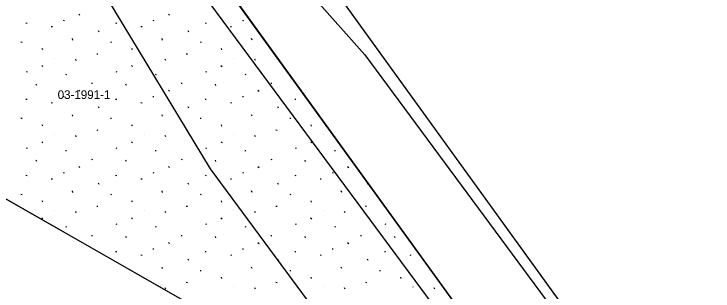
# Model space of a CAD drawing. Extents: x 413946 to 415528, y 4453939 to 4454944.
# Drawn here: x 414117.8 to 414198.6, y 4454721 to 4454753 of the extents above; entities that cross this region are included whole.
import ezdxf

# ---------------------------------------------------------------- set-up
doc = ezdxf.new("R2010")
doc.units = 0
for name, color, linetype in [('0_KADASTRO', 7, 'Continuous'), ('HAT_ENERJI_NAKIL_HAT', 7, 'Continuous'), ('KST_ENERJI_NAKIL_HAT', 7, 'Continuous'), ('Level 28', 7, 'Continuous'), ('Level 41', 7, 'Continuous'), ('Level 54', 7, 'Continuous')]:
    doc.layers.add(name, color=color, linetype=linetype)

msp = doc.modelspace()

# ---------------------------------------------------------------- linework, layer by layer
at = {"layer": '0_KADASTRO'}
for points in [[(414096.99, 4454835.77), (414098.7, 4454839.14), (414238.98, 4454892.53), (414254.93, 4454896.1), (414267.24, 4454897.45), (414291.64, 4454897.36), (414301.38, 4454895.97), (414237.57, 4454666.8), (414236.56, 4454663.13), (414213.19, 4454675.19), (414204.39, 4454687.27), (414188.47, 4454709.34), (414167.47, 4454738.38)], [(414085.37, 4454749.55), (414107.18, 4454790.27), (414110.22, 4454795.94), (414114.42, 4454794.63), (414180.37, 4454703.49), (414185.88, 4454695.87), (414185.72, 4454695.34), (414184.91, 4454692.77), (414168.2, 4454702.3), (414160.59, 4454706.64)]]:
    msp.add_lwpolyline(points, close=True, dxfattribs=at)
at = {"layer": 'HAT_ENERJI_NAKIL_HAT'}
msp.add_lwpolyline([(414658.516, 4453939.478), (414647.224, 4454070.234), (413999.883, 4454943.957)], dxfattribs=at)
at = {"layer": 'KST_ENERJI_NAKIL_HAT'}
for p, q in [((414107.065, 4454805.782), (414158.371, 4454748.301)), ((414140.517, 4454735.108), (414100.636, 4454801.021)), ((414158.371, 4454748.301), (414184.473, 4454712.979)), ((414230.556, 4454613.267), (414140.517, 4454735.108))]:
    msp.add_line(p, q, dxfattribs=at)
at = {"layer": 'Level 28'}
for p, q in [((414167.47, 4454738.38), (414096.99, 4454835.77)), ((414114.42, 4454794.63), (414185.88, 4454695.87)), ((414184.91, 4454692.77), (414085.37, 4454749.55)), ((414188.47, 4454709.34), (414167.47, 4454738.38))]:
    msp.add_line(p, q, dxfattribs=at)
at = {"layer": 'Level 41'}
for p, q in [((414125.262, 4454752.989), (414125.389, 4454752.889)), ((414125.262, 4454752.989), (414125.389, 4454752.889)), ((414135.63, 4454752.989), (414135.757, 4454752.889)), ((414135.63, 4454752.989), (414135.757, 4454752.889)), ((414119.162, 4454751.979), (414119.288, 4454751.956)), ((414119.162, 4454751.979), (414119.288, 4454751.956)), ((414122.091, 4454751.569), (414122.217, 4454751.545)), ((414122.091, 4454751.569), (414122.217, 4454751.545)), ((414123.467, 4454752.283), (414123.593, 4454752.26)), ((414123.467, 4454752.283), (414123.593, 4454752.26)), ((414129.53, 4454751.979), (414129.656, 4454751.956)), ((414129.53, 4454751.979), (414129.656, 4454751.956)), ((414132.459, 4454751.569), (414132.585, 4454751.545)), ((414132.459, 4454751.569), (414132.585, 4454751.545)), ((414133.835, 4454752.283), (414133.961, 4454752.26)), ((414133.835, 4454752.283), (414133.961, 4454752.26)), ((414139.898, 4454751.979), (414140.024, 4454751.956)), ((414139.898, 4454751.979), (414140.024, 4454751.956)), ((414142.827, 4454751.569), (414142.953, 4454751.545)), ((414142.827, 4454751.569), (414142.953, 4454751.545)), ((414144.203, 4454752.283), (414144.329, 4454752.26)), ((414144.203, 4454752.283), (414144.329, 4454752.26)), ((414127.627, 4454750.91), (414127.561, 4454751.072)), ((414127.627, 4454750.91), (414127.561, 4454751.072)), ((414137.995, 4454750.91), (414137.929, 4454751.072)), ((414137.995, 4454750.91), (414137.929, 4454751.072)), ((414124.596, 4454749.995), (414124.531, 4454750.159)), ((414124.596, 4454749.995), (414124.531, 4454750.159)), ((414134.964, 4454749.995), (414134.899, 4454750.159)), ((414134.964, 4454749.995), (414134.899, 4454750.159)), ((414145.332, 4454749.995), (414145.267, 4454750.159)), ((414145.332, 4454749.995), (414145.267, 4454750.159)), ((414118.578, 4454749.775), (414118.704, 4454749.751)), ((414118.578, 4454749.775), (414118.704, 4454749.751)), ((414128.946, 4454749.775), (414129.072, 4454749.751)), ((414128.946, 4454749.775), (414129.072, 4454749.751)), ((414139.314, 4454749.775), (414139.44, 4454749.751)), ((414139.314, 4454749.775), (414139.44, 4454749.751)), ((414121.1, 4454748.846), (414121.036, 4454749.007)), ((414121.1, 4454748.846), (414121.036, 4454749.007)), ((414127.342, 4454748.407), (414127.468, 4454748.383)), ((414127.342, 4454748.407), (414127.468, 4454748.383)), ((414131.468, 4454748.846), (414131.404, 4454749.007)), ((414131.468, 4454748.846), (414131.404, 4454749.007)), ((414137.71, 4454748.407), (414137.836, 4454748.383)), ((414137.71, 4454748.407), (414137.836, 4454748.383)), ((414141.836, 4454748.846), (414141.772, 4454749.007)), ((414141.836, 4454748.846), (414141.772, 4454749.007)), ((414122.458, 4454747.882), (414122.466, 4454747.881)), ((414122.458, 4454747.882), (414122.466, 4454747.881)), ((414124.977, 4454747.613), (414124.912, 4454747.775)), ((414124.977, 4454747.613), (414124.912, 4454747.775)), ((414132.826, 4454747.882), (414132.834, 4454747.881)), ((414132.826, 4454747.882), (414132.834, 4454747.881)), ((414135.345, 4454747.613), (414135.28, 4454747.775)), ((414135.345, 4454747.613), (414135.28, 4454747.775)), ((414143.194, 4454747.882), (414143.202, 4454747.881)), ((414143.194, 4454747.882), (414143.202, 4454747.881)), ((414145.713, 4454747.613), (414145.648, 4454747.775)), ((414145.713, 4454747.613), (414145.648, 4454747.775)), ((414120.983, 4454747.044), (414121.11, 4454746.945)), ((414120.983, 4454747.044), (414121.11, 4454746.945)), ((414131.351, 4454747.044), (414131.478, 4454746.945)), ((414131.351, 4454747.044), (414131.478, 4454746.945)), ((414141.719, 4454747.044), (414141.846, 4454746.945)), ((414141.719, 4454747.044), (414141.846, 4454746.945)), ((414119.189, 4454746.339), (414119.315, 4454746.314)), ((414119.189, 4454746.339), (414119.315, 4454746.314)), ((414123.737, 4454746.045), (414123.863, 4454746.021)), ((414123.737, 4454746.045), (414123.863, 4454746.021)), ((414129.557, 4454746.339), (414129.683, 4454746.314)), ((414129.557, 4454746.339), (414129.683, 4454746.314)), ((414134.105, 4454746.045), (414134.231, 4454746.021)), ((414134.105, 4454746.045), (414134.231, 4454746.021)), ((414139.925, 4454746.339), (414140.051, 4454746.314)), ((414139.925, 4454746.339), (414140.051, 4454746.314)), ((414144.473, 4454746.045), (414144.599, 4454746.021)), ((414144.473, 4454746.045), (414144.599, 4454746.021)), ((414126.737, 4454745.021), (414126.862, 4454744.996)), ((414126.737, 4454745.021), (414126.862, 4454744.996)), ((414137.105, 4454745.021), (414137.23, 4454744.996)), ((414137.105, 4454745.021), (414137.23, 4454744.996)), ((414147.473, 4454745.021), (414147.598, 4454744.996)), ((414147.473, 4454745.021), (414147.598, 4454744.996)), ((414120.402, 4454744.741), (414120.337, 4454744.903)), ((414120.402, 4454744.741), (414120.337, 4454744.903)), ((414130.77, 4454744.741), (414130.705, 4454744.903)), ((414130.77, 4454744.741), (414130.705, 4454744.903)), ((414141.138, 4454744.741), (414141.073, 4454744.903)), ((414141.138, 4454744.741), (414141.073, 4454744.903)), ((414123.467, 4454743.477), (414123.593, 4454743.454)), ((414123.467, 4454743.477), (414123.593, 4454743.454)), ((414125.262, 4454744.183), (414125.389, 4454744.083)), ((414125.262, 4454744.183), (414125.389, 4454744.083)), ((414133.835, 4454743.477), (414133.961, 4454743.454)), ((414133.835, 4454743.477), (414133.961, 4454743.454)), ((414135.63, 4454744.183), (414135.757, 4454744.083)), ((414135.63, 4454744.183), (414135.757, 4454744.083)), ((414144.203, 4454743.477), (414144.329, 4454743.454)), ((414144.203, 4454743.477), (414144.329, 4454743.454)), ((414145.998, 4454744.183), (414146.125, 4454744.083)), ((414145.998, 4454744.183), (414146.125, 4454744.083)), ((414119.162, 4454743.173), (414119.288, 4454743.15)), ((414119.162, 4454743.173), (414119.288, 4454743.15)), ((414122.091, 4454742.763), (414122.217, 4454742.739)), ((414122.091, 4454742.763), (414122.217, 4454742.739)), ((414129.53, 4454743.173), (414129.656, 4454743.15)), ((414129.53, 4454743.173), (414129.656, 4454743.15)), ((414132.459, 4454742.763), (414132.585, 4454742.739)), ((414132.459, 4454742.763), (414132.585, 4454742.739)), ((414139.898, 4454743.173), (414140.024, 4454743.15)), ((414139.898, 4454743.173), (414140.024, 4454743.15)), ((414142.827, 4454742.763), (414142.953, 4454742.739)), ((414142.827, 4454742.763), (414142.953, 4454742.739)), ((414150.266, 4454743.173), (414150.392, 4454743.15)), ((414150.266, 4454743.173), (414150.392, 4454743.15)), ((414127.627, 4454742.104), (414127.561, 4454742.266)), ((414127.627, 4454742.104), (414127.561, 4454742.266)), ((414137.995, 4454742.104), (414137.929, 4454742.266)), ((414137.995, 4454742.104), (414137.929, 4454742.266)), ((414148.363, 4454742.104), (414148.297, 4454742.266)), ((414148.363, 4454742.104), (414148.297, 4454742.266)), ((414124.596, 4454741.189), (414124.531, 4454741.353)), ((414124.596, 4454741.189), (414124.531, 4454741.353)), ((414134.964, 4454741.189), (414134.899, 4454741.353)), ((414134.964, 4454741.189), (414134.899, 4454741.353)), ((414145.332, 4454741.189), (414145.267, 4454741.353)), ((414145.332, 4454741.189), (414145.267, 4454741.353)), ((414118.578, 4454740.969), (414118.704, 4454740.945)), ((414118.578, 4454740.969), (414118.704, 4454740.945)), ((414121.1, 4454740.04), (414121.036, 4454740.201)), ((414121.1, 4454740.04), (414121.036, 4454740.201)), ((414128.946, 4454740.969), (414129.072, 4454740.945)), ((414128.946, 4454740.969), (414129.072, 4454740.945)), ((414131.468, 4454740.04), (414131.404, 4454740.201)), ((414131.468, 4454740.04), (414131.404, 4454740.201)), ((414139.314, 4454740.969), (414139.44, 4454740.945)), ((414139.314, 4454740.969), (414139.44, 4454740.945)), ((414141.836, 4454740.04), (414141.772, 4454740.201)), ((414141.836, 4454740.04), (414141.772, 4454740.201)), ((414149.682, 4454740.969), (414149.808, 4454740.945)), ((414149.682, 4454740.969), (414149.808, 4454740.945)), ((414152.204, 4454740.04), (414152.14, 4454740.201)), ((414152.204, 4454740.04), (414152.14, 4454740.201)), ((414127.342, 4454739.601), (414127.468, 4454739.577)), ((414127.342, 4454739.601), (414127.468, 4454739.577)), ((414137.71, 4454739.601), (414137.836, 4454739.577)), ((414137.71, 4454739.601), (414137.836, 4454739.577)), ((414148.078, 4454739.601), (414148.204, 4454739.577)), ((414148.078, 4454739.601), (414148.204, 4454739.577)), ((414122.458, 4454739.076), (414122.466, 4454739.075)), ((414122.458, 4454739.076), (414122.466, 4454739.075)), ((414124.977, 4454738.807), (414124.912, 4454738.969)), ((414124.977, 4454738.807), (414124.912, 4454738.969)), ((414132.826, 4454739.076), (414132.834, 4454739.075)), ((414132.826, 4454739.076), (414132.834, 4454739.075)), ((414135.345, 4454738.807), (414135.28, 4454738.969)), ((414135.345, 4454738.807), (414135.28, 4454738.969)), ((414143.194, 4454739.076), (414143.202, 4454739.075)), ((414143.194, 4454739.076), (414143.202, 4454739.075)), ((414145.713, 4454738.807), (414145.648, 4454738.969)), ((414145.713, 4454738.807), (414145.648, 4454738.969)), ((414153.562, 4454739.076), (414153.57, 4454739.075)), ((414153.562, 4454739.076), (414153.57, 4454739.075)), ((414120.983, 4454738.238), (414121.11, 4454738.139)), ((414120.983, 4454738.238), (414121.11, 4454738.139)), ((414131.351, 4454738.238), (414131.478, 4454738.139)), ((414131.351, 4454738.238), (414131.478, 4454738.139)), ((414141.719, 4454738.238), (414141.846, 4454738.139)), ((414141.719, 4454738.238), (414141.846, 4454738.139)), ((414152.087, 4454738.238), (414152.214, 4454738.139)), ((414152.087, 4454738.238), (414152.214, 4454738.139)), ((414119.189, 4454737.533), (414119.315, 4454737.508)), ((414119.189, 4454737.533), (414119.315, 4454737.508)), ((414123.737, 4454737.239), (414123.863, 4454737.215)), ((414123.737, 4454737.239), (414123.863, 4454737.215)), ((414129.557, 4454737.533), (414129.683, 4454737.508)), ((414129.557, 4454737.533), (414129.683, 4454737.508)), ((414134.105, 4454737.239), (414134.231, 4454737.215)), ((414134.105, 4454737.239), (414134.231, 4454737.215)), ((414139.925, 4454737.533), (414140.051, 4454737.508)), ((414139.925, 4454737.533), (414140.051, 4454737.508)), ((414144.473, 4454737.239), (414144.599, 4454737.215)), ((414144.473, 4454737.239), (414144.599, 4454737.215)), ((414150.293, 4454737.533), (414150.419, 4454737.508)), ((414150.293, 4454737.533), (414150.419, 4454737.508)), ((414154.841, 4454737.239), (414154.967, 4454737.215)), ((414154.841, 4454737.239), (414154.967, 4454737.215)), ((414126.737, 4454736.215), (414126.862, 4454736.19)), ((414126.737, 4454736.215), (414126.862, 4454736.19)), ((414137.105, 4454736.215), (414137.23, 4454736.19)), ((414137.105, 4454736.215), (414137.23, 4454736.19)), ((414147.473, 4454736.215), (414147.598, 4454736.19)), ((414147.473, 4454736.215), (414147.598, 4454736.19)), ((414120.402, 4454735.935), (414120.337, 4454736.097)), ((414120.402, 4454735.935), (414120.337, 4454736.097)), ((414125.262, 4454735.377), (414125.389, 4454735.277)), ((414125.262, 4454735.377), (414125.389, 4454735.277)), ((414130.77, 4454735.935), (414130.705, 4454736.097)), ((414130.77, 4454735.935), (414130.705, 4454736.097)), ((414135.63, 4454735.377), (414135.757, 4454735.277)), ((414135.63, 4454735.377), (414135.757, 4454735.277)), ((414141.138, 4454735.935), (414141.073, 4454736.097)), ((414141.138, 4454735.935), (414141.073, 4454736.097)), ((414145.998, 4454735.377), (414146.125, 4454735.277)), ((414145.998, 4454735.377), (414146.125, 4454735.277)), ((414151.506, 4454735.935), (414151.441, 4454736.097)), ((414151.506, 4454735.935), (414151.441, 4454736.097)), ((414156.366, 4454735.377), (414156.493, 4454735.277)), ((414156.366, 4454735.377), (414156.493, 4454735.277)), ((414123.467, 4454734.671), (414123.593, 4454734.648)), ((414123.467, 4454734.671), (414123.593, 4454734.648)), ((414133.835, 4454734.671), (414133.961, 4454734.648)), ((414133.835, 4454734.671), (414133.961, 4454734.648)), ((414144.203, 4454734.671), (414144.329, 4454734.648)), ((414144.203, 4454734.671), (414144.329, 4454734.648)), ((414154.571, 4454734.671), (414154.697, 4454734.648)), ((414154.571, 4454734.671), (414154.697, 4454734.648)), ((414119.162, 4454734.367), (414119.288, 4454734.344)), ((414119.162, 4454734.367), (414119.288, 4454734.344)), ((414122.091, 4454733.957), (414122.217, 4454733.933)), ((414122.091, 4454733.957), (414122.217, 4454733.933)), ((414129.53, 4454734.367), (414129.656, 4454734.344)), ((414129.53, 4454734.367), (414129.656, 4454734.344)), ((414132.459, 4454733.957), (414132.585, 4454733.933)), ((414132.459, 4454733.957), (414132.585, 4454733.933)), ((414139.898, 4454734.367), (414140.024, 4454734.344)), ((414139.898, 4454734.367), (414140.024, 4454734.344)), ((414142.827, 4454733.957), (414142.953, 4454733.933)), ((414142.827, 4454733.957), (414142.953, 4454733.933)), ((414150.266, 4454734.367), (414150.392, 4454734.344)), ((414150.266, 4454734.367), (414150.392, 4454734.344)), ((414153.195, 4454733.957), (414153.321, 4454733.933)), ((414153.195, 4454733.957), (414153.321, 4454733.933)), ((414127.627, 4454733.298), (414127.561, 4454733.46)), ((414127.627, 4454733.298), (414127.561, 4454733.46)), ((414137.995, 4454733.298), (414137.929, 4454733.46)), ((414137.995, 4454733.298), (414137.929, 4454733.46)), ((414148.363, 4454733.298), (414148.297, 4454733.46)), ((414148.363, 4454733.298), (414148.297, 4454733.46)), ((414158.731, 4454733.298), (414158.665, 4454733.46)), ((414158.731, 4454733.298), (414158.665, 4454733.46)), ((414118.578, 4454732.163), (414118.704, 4454732.139)), ((414118.578, 4454732.163), (414118.704, 4454732.139)), ((414124.596, 4454732.383), (414124.531, 4454732.547)), ((414124.596, 4454732.383), (414124.531, 4454732.547)), ((414128.946, 4454732.163), (414129.072, 4454732.139)), ((414128.946, 4454732.163), (414129.072, 4454732.139)), ((414134.964, 4454732.383), (414134.899, 4454732.547)), ((414134.964, 4454732.383), (414134.899, 4454732.547)), ((414139.314, 4454732.163), (414139.44, 4454732.139)), ((414139.314, 4454732.163), (414139.44, 4454732.139)), ((414145.332, 4454732.383), (414145.267, 4454732.547)), ((414145.332, 4454732.383), (414145.267, 4454732.547)), ((414149.682, 4454732.163), (414149.808, 4454732.139)), ((414149.682, 4454732.163), (414149.808, 4454732.139)), ((414155.7, 4454732.383), (414155.635, 4454732.547)), ((414155.7, 4454732.383), (414155.635, 4454732.547)), ((414121.1, 4454731.234), (414121.036, 4454731.395)), ((414121.1, 4454731.234), (414121.036, 4454731.395)), ((414131.468, 4454731.234), (414131.404, 4454731.395)), ((414131.468, 4454731.234), (414131.404, 4454731.395)), ((414141.836, 4454731.234), (414141.772, 4454731.395)), ((414141.836, 4454731.234), (414141.772, 4454731.395)), ((414152.204, 4454731.234), (414152.14, 4454731.395)), ((414152.204, 4454731.234), (414152.14, 4454731.395)), ((414127.342, 4454730.795), (414127.468, 4454730.771)), ((414127.342, 4454730.795), (414127.468, 4454730.771)), ((414137.71, 4454730.795), (414137.836, 4454730.771)), ((414137.71, 4454730.795), (414137.836, 4454730.771)), ((414148.078, 4454730.795), (414148.204, 4454730.771)), ((414148.078, 4454730.795), (414148.204, 4454730.771)), ((414158.446, 4454730.795), (414158.572, 4454730.771)), ((414158.446, 4454730.795), (414158.572, 4454730.771)), ((414122.458, 4454730.27), (414122.466, 4454730.269)), ((414122.458, 4454730.27), (414122.466, 4454730.269)), ((414124.977, 4454730.001), (414124.912, 4454730.163)), ((414124.977, 4454730.001), (414124.912, 4454730.163)), ((414132.826, 4454730.27), (414132.834, 4454730.269)), ((414132.826, 4454730.27), (414132.834, 4454730.269)), ((414135.345, 4454730.001), (414135.28, 4454730.163)), ((414135.345, 4454730.001), (414135.28, 4454730.163)), ((414143.194, 4454730.27), (414143.202, 4454730.269)), ((414143.194, 4454730.27), (414143.202, 4454730.269)), ((414145.713, 4454730.001), (414145.648, 4454730.163)), ((414145.713, 4454730.001), (414145.648, 4454730.163)), ((414153.562, 4454730.27), (414153.57, 4454730.269)), ((414153.562, 4454730.27), (414153.57, 4454730.269)), ((414156.081, 4454730.001), (414156.016, 4454730.163)), ((414156.081, 4454730.001), (414156.016, 4454730.163)), ((414120.983, 4454729.432), (414121.11, 4454729.333)), ((414120.983, 4454729.432), (414121.11, 4454729.333)), ((414131.351, 4454729.432), (414131.478, 4454729.333)), ((414131.351, 4454729.432), (414131.478, 4454729.333)), ((414141.719, 4454729.432), (414141.846, 4454729.333)), ((414141.719, 4454729.432), (414141.846, 4454729.333)), ((414152.087, 4454729.432), (414152.214, 4454729.333)), ((414152.087, 4454729.432), (414152.214, 4454729.333)), ((414123.737, 4454728.433), (414123.863, 4454728.409)), ((414123.737, 4454728.433), (414123.863, 4454728.409)), ((414129.557, 4454728.727), (414129.683, 4454728.702)), ((414129.557, 4454728.727), (414129.683, 4454728.702)), ((414134.105, 4454728.433), (414134.231, 4454728.409)), ((414134.105, 4454728.433), (414134.231, 4454728.409)), ((414139.925, 4454728.727), (414140.051, 4454728.702)), ((414139.925, 4454728.727), (414140.051, 4454728.702)), ((414144.473, 4454728.433), (414144.599, 4454728.409)), ((414144.473, 4454728.433), (414144.599, 4454728.409)), ((414150.293, 4454728.727), (414150.419, 4454728.702)), ((414150.293, 4454728.727), (414150.419, 4454728.702)), ((414154.841, 4454728.433), (414154.967, 4454728.409)), ((414154.841, 4454728.433), (414154.967, 4454728.409)), ((414160.661, 4454728.727), (414160.787, 4454728.702)), ((414160.661, 4454728.727), (414160.787, 4454728.702)), ((414126.737, 4454727.409), (414126.862, 4454727.384)), ((414126.737, 4454727.409), (414126.862, 4454727.384)), ((414130.77, 4454727.129), (414130.705, 4454727.291)), ((414130.77, 4454727.129), (414130.705, 4454727.291)), ((414137.105, 4454727.409), (414137.23, 4454727.384)), ((414137.105, 4454727.409), (414137.23, 4454727.384)), ((414141.138, 4454727.129), (414141.073, 4454727.291)), ((414141.138, 4454727.129), (414141.073, 4454727.291)), ((414147.473, 4454727.409), (414147.598, 4454727.384)), ((414147.473, 4454727.409), (414147.598, 4454727.384)), ((414151.506, 4454727.129), (414151.441, 4454727.291)), ((414151.506, 4454727.129), (414151.441, 4454727.291)), ((414157.841, 4454727.409), (414157.966, 4454727.384)), ((414157.841, 4454727.409), (414157.966, 4454727.384)), ((414161.874, 4454727.129), (414161.809, 4454727.291)), ((414161.874, 4454727.129), (414161.809, 4454727.291)), ((414135.63, 4454726.571), (414135.757, 4454726.471)), ((414135.63, 4454726.571), (414135.757, 4454726.471)), ((414145.998, 4454726.571), (414146.125, 4454726.471)), ((414145.998, 4454726.571), (414146.125, 4454726.471)), ((414156.366, 4454726.571), (414156.493, 4454726.471)), ((414156.366, 4454726.571), (414156.493, 4454726.471)), ((414133.835, 4454725.865), (414133.961, 4454725.842)), ((414133.835, 4454725.865), (414133.961, 4454725.842)), ((414144.203, 4454725.865), (414144.329, 4454725.842)), ((414144.203, 4454725.865), (414144.329, 4454725.842)), ((414154.571, 4454725.865), (414154.697, 4454725.842)), ((414154.571, 4454725.865), (414154.697, 4454725.842)), ((414129.53, 4454725.561), (414129.656, 4454725.538)), ((414129.53, 4454725.561), (414129.656, 4454725.538)), ((414132.459, 4454725.151), (414132.585, 4454725.127)), ((414132.459, 4454725.151), (414132.585, 4454725.127)), ((414139.898, 4454725.561), (414140.024, 4454725.538)), ((414139.898, 4454725.561), (414140.024, 4454725.538)), ((414142.827, 4454725.151), (414142.953, 4454725.127)), ((414142.827, 4454725.151), (414142.953, 4454725.127)), ((414150.266, 4454725.561), (414150.392, 4454725.538)), ((414150.266, 4454725.561), (414150.392, 4454725.538)), ((414153.195, 4454725.151), (414153.321, 4454725.127)), ((414153.195, 4454725.151), (414153.321, 4454725.127)), ((414160.634, 4454725.561), (414160.76, 4454725.538)), ((414160.634, 4454725.561), (414160.76, 4454725.538)), ((414163.563, 4454725.151), (414163.689, 4454725.127)), ((414163.563, 4454725.151), (414163.689, 4454725.127)), ((414137.995, 4454724.492), (414137.929, 4454724.654)), ((414137.995, 4454724.492), (414137.929, 4454724.654)), ((414148.363, 4454724.492), (414148.297, 4454724.654)), ((414148.363, 4454724.492), (414148.297, 4454724.654)), ((414158.731, 4454724.492), (414158.665, 4454724.654)), ((414158.731, 4454724.492), (414158.665, 4454724.654)), ((414134.964, 4454723.577), (414134.899, 4454723.741)), ((414134.964, 4454723.577), (414134.899, 4454723.741)), ((414139.314, 4454723.357), (414139.44, 4454723.333)), ((414139.314, 4454723.357), (414139.44, 4454723.333)), ((414145.332, 4454723.577), (414145.267, 4454723.741)), ((414145.332, 4454723.577), (414145.267, 4454723.741)), ((414149.682, 4454723.357), (414149.808, 4454723.333)), ((414149.682, 4454723.357), (414149.808, 4454723.333)), ((414155.7, 4454723.577), (414155.635, 4454723.741)), ((414155.7, 4454723.577), (414155.635, 4454723.741)), ((414160.05, 4454723.357), (414160.176, 4454723.333)), ((414160.05, 4454723.357), (414160.176, 4454723.333)), ((414141.836, 4454722.428), (414141.772, 4454722.589)), ((414141.836, 4454722.428), (414141.772, 4454722.589)), ((414152.204, 4454722.428), (414152.14, 4454722.589)), ((414152.204, 4454722.428), (414152.14, 4454722.589)), ((414162.572, 4454722.428), (414162.508, 4454722.589)), ((414162.572, 4454722.428), (414162.508, 4454722.589)), ((414137.71, 4454721.989), (414137.836, 4454721.965)), ((414137.71, 4454721.989), (414137.836, 4454721.965)), ((414148.078, 4454721.989), (414148.204, 4454721.965)), ((414148.078, 4454721.989), (414148.204, 4454721.965)), ((414158.446, 4454721.989), (414158.572, 4454721.965)), ((414158.446, 4454721.989), (414158.572, 4454721.965)), ((414135.345, 4454721.195), (414135.28, 4454721.357)), ((414135.345, 4454721.195), (414135.28, 4454721.357)), ((414143.194, 4454721.464), (414143.202, 4454721.463)), ((414143.194, 4454721.464), (414143.202, 4454721.463)), ((414145.713, 4454721.195), (414145.648, 4454721.357)), ((414145.713, 4454721.195), (414145.648, 4454721.357)), ((414153.562, 4454721.464), (414153.57, 4454721.463)), ((414153.562, 4454721.464), (414153.57, 4454721.463)), ((414156.081, 4454721.195), (414156.016, 4454721.357)), ((414156.081, 4454721.195), (414156.016, 4454721.357)), ((414163.93, 4454721.464), (414163.938, 4454721.463)), ((414163.93, 4454721.464), (414163.938, 4454721.463)), ((414166.449, 4454721.195), (414166.384, 4454721.357)), ((414166.449, 4454721.195), (414166.384, 4454721.357))]:
    msp.add_line(p, q, dxfattribs=at)
at = {"layer": 'Level 54'}
msp.add_lwpolyline([(414098.7, 4454839.14), (414238.98, 4454892.53), (414254.93, 4454896.1), (414267.24, 4454897.45), (414291.64, 4454897.36), (414301.38, 4454895.97), (414237.57, 4454666.8), (414236.56, 4454663.13), (414213.19, 4454675.19), (414204.39, 4454687.27), (414188.47, 4454709.34), (414167.47, 4454738.38), (414096.99, 4454835.77), (414098.7, 4454839.14)], close=True, dxfattribs=at)

# ---------------------------------------------------------------- texts
at = {"layer": '0_KADASTRO'}
msp.add_text('03-1991-1', height=1, dxfattribs=at).set_placement((414122.825, 4454743.18))

doc.saveas('drawing.dxf')
